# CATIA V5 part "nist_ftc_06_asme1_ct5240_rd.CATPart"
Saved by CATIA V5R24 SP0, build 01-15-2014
Part number: NIST PMI FTC 06 ASME1
Revision: D
Description: NIST PMI test model downloaded from http://go.usa.gov/mGVm
Bounding box of the stored display mesh (mm): x -152.4 to 152.4, y 0 to 97.79, z -247.65 to 0
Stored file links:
  C:\work\NIST\DCC_review\nist_ftc_06_asme1_ct5240_rd.CATPart
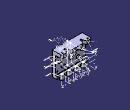
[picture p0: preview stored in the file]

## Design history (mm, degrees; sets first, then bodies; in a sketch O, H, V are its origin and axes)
f4a2d38f3ddc11d3a929006094b99c4b_11 "CATTPSSet"
TTRSSet1
Set1 "Geom_for_MBD_A_notes"
  Plane1: type Equation, A -0.57735, B -0.57735, C 0.57735, Length 229.55, RefPoint vertex [face of Pad1 from Sketch12.L1 | face of Pad1 from Sketch12.L2 | end face of Pad1], RefAxis AxisSystem5
Set2 "MBD_A"
  AxisSystem1 "F1": origin (108.585, 50.8, -209.55), X (-1, 0, 0), Y (0, 1, 0), Z (0, 0, -1)
  AxisSystem2 "F2": origin (36.195, 50.8, -209.55), X (-1, 0, 0), Y (0, 1, 0), Z (0, 0, -1)
  AxisSystem3 "F3": origin (-36.195, 50.8, -209.55), X (-1, 0, 0), Y (0, 1, 0), Z (0, 0, -1)
  AxisSystem4 "F4": origin (-108.585, 50.8, -209.55), X (-1, 0, 0), Y (0, 1, 0), Z (0, 0, -1)
  AxisSystem5 "EAB": origin (0, 0, -209.55), X (-1, 0, 0), Y (0, 0, 1), Z (0, 1, 0)
Set3 "MBD_C"
  AxisSystem6 "DCJ": origin (82.55, 31.75, 0), X (1, 0, 0), Y (0, 0, -1), Z (0, 1, 0)
  AxisSystem7 "DCK": origin (-82.55, 31.75, 0), X (1, 0, 0), Y (0, 0, -1), Z (0, 1, 0)
  AxisSystem8 "DG": origin (76.2, 31.75, -158.75), X (0, 0, -1), Y (-1, 0, 0), Z (0, 1, 0)
  AxisSystem9 "DH": origin (-76.2, 31.75, -158.75), X (0, 0, -1), Y (-1, 0, 0), Z (0, 1, 0)
  Sketch1 on face of Pocket1 from Sketch15.L6, origin (-87.885, 40.9814, 0), H (-0.4226, -0.9063, 0), V (0, 0, 1)
    line L1 (-45.8598, -31.75) -> (-45.8598, 0)
    point P1 (-45.8598, -31.75)
    reference projected point E1 (-45.8598, -31.75) from Sketch10.P5
    vertical: L1 V
    coincidence: P1 E1
  Sketch2 on face of RectPattern2, origin (87.885, 40.9814, 0), H (-0.4226, 0.9063, 0), V (0, 0, 1)
    line L1 (45.8598, -31.75) -> (45.8598, 0)
    point P1 (45.8598, -31.75)
    reference projected point E1 (45.8598, -31.75) from Sketch9.P6
    vertical: L1 V
    coincidence: P1 E1
  Sketch3 on face of RectPattern2, origin (47.7271, -22.2555, 0), H (-0.4226, -0.9063, 0), V (0, 0, 1)
    line L1 (-115.6341, -31.75) -> (-115.6341, 0)
    point P1 (-115.6341, -31.75)
    reference projected point E1 (-115.6341, -31.75) from Sketch9.P5
    vertical: L1 V
    coincidence: P1 E1
  Sketch4 on Plane6, origin (0, 66.04, 0), H (-1, 0, 0), V (0, 0, 1)
    circle A1 centre (76.2, -158.75) radius 12.7
    point P1 (76.2, -158.75)
    reference projected point E1 (76.2, -158.75) from axis of face of RectPattern7
    circle A2 centre (-76.2, -158.75) radius 12.7
    point P2 (-76.2, -158.75)
    reference projected point E2 (-76.2, -158.75) from axis of face of Hole4
    radius A1 = 12.7
    radius A2 = 12.7
    coincidence: E1 P1, E2 P2
  Sketch5 on face of RectPattern2, origin (47.7271, -22.2555, 0), H (-0.4226, -0.9063, 0), V (0, 0, 1)
    projected line E1 (-132.4556, 0) -> (-97.4233, 0) from edge [face of RectPattern2 | face of Pad1 from Sketch12.L1]
    projected line E2 (-132.4556, -31.75) -> (-97.4233, -31.75) from edge [face of Pad1 from Sketch12.L7 | face of RectPattern2]
    line L1 (-97.4233, 0) -> (-115.6341, 0)
    point P5 (-114.9395, 0)
    line L2 (-115.6341, -31.75) -> (-97.4233, -31.75)
    point P6 (-115.6341, -31.75)
    line L3 (-97.4233, 0) -> (-97.4233, -31.75)
    line L4 (-115.6341, 0) -> (-115.6341, -31.75)
    reference projected line E3 (-115.6341, -31.75) -> (-115.6341, 0) from Sketch3
    midpoint: P5 E1
    horizontal: L1 H, L2 H
    coincidence: P6 E2, E3 L4
    vertical: L3 V, L4 V
  Sketch6 on face of RectPattern2, origin (87.885, 40.9814, 0), H (-0.4226, 0.9063, 0), V (0, 0, 1)
    projected line E1 (62.6813, 0) -> (27.6491, 0) from edge [face of Pad1 from Sketch12.L1 | face of RectPattern2]
    projected line E2 (45.8598, 0) -> (27.6491, 0) from edge [face of Pad1 from Sketch12.L1 | face of RectPattern2]
    projected line E3 (27.6491, -31.75) -> (27.6491, 0) from edge [face of RectPattern2 | face of RectPattern2]
    projected line E4 (27.6491, -31.75) -> (62.6813, -31.75) from edge [face of Pad1 from Sketch12.L7 | face of RectPattern2]
    projected line E5 (27.6491, -31.75) -> (45.8598, -31.75) from edge [face of Pad1 from Sketch12.L7 | face of RectPattern2]
    projected line E6 (45.8598, -31.75) -> (45.8598, 0) from Sketch2.L1
  Sketch7 on face of Pocket1 from Sketch15.L6, origin (-87.885, 40.9814, 0), H (-0.4226, -0.9063, 0), V (0, 0, 1)
    projected line E1 (-62.6813, 0) -> (-27.6491, 0) from edge [face of Pocket1 from Sketch15.L6 | face of Pad1 from Sketch12.L1]
    projected line E2 (-45.8598, 0) -> (-27.6491, 0) from edge [face of Pocket1 from Sketch15.L6 | face of Pad1 from Sketch12.L1]
    projected line E3 (-62.6813, -31.75) -> (-27.6491, -31.75) from edge [face of Pad1 from Sketch12.L7 | face of Pocket1 from Sketch15.L6]
    projected line E4 (-45.8598, -31.75) -> (-27.6491, -31.75) from edge [face of Pad1 from Sketch12.L7 | face of Pocket1 from Sketch15.L6]
    projected line E5 (-27.6491, -31.75) -> (-27.6491, 0) from edge [face of Pocket1 from Sketch15.L5 | face of Pocket1 from Sketch15.L6]
    projected line E6 (-45.8598, -31.75) -> (-45.8598, 0) from Sketch1.L1
  Sketch8 on face of Pocket1 from Sketch15.L1, origin (-47.7271, -22.2555, 0), H (-0.4226, 0.9063, 0), V (0, 0, 1)
    projected line E1 (97.4233, -31.75) -> (132.4556, -31.75) from edge [face of Pad1 from Sketch12.L7 | face of Pocket1 from Sketch15.L1]
    projected line E2 (97.4233, -31.75) -> (115.6341, -31.75) from edge [face of Pad1 from Sketch12.L7 | face of Pocket1 from Sketch15.L1]
    projected line E3 (97.4233, -31.75) -> (97.4233, 0) from edge [face of Pocket1 from Sketch15.L1 | face of Pocket1 from Sketch15.L2]
    projected line E4 (132.4556, 0) -> (97.4233, 0) from edge [face of Pad1 from Sketch12.L1 | face of Pocket1 from Sketch15.L1]
    projected line E5 (115.6341, 0) -> (97.4233, 0) from edge [face of Pad1 from Sketch12.L1 | face of Pocket1 from Sketch15.L1]
    projected line E6 (115.6341, -31.75) -> (115.6341, 0) from Sketch11.L1
    construction line L1 through (0, 0) direction (0, 1)
  Sketch9 on face of Pad1 from Sketch12.L7, origin (0, 0, -31.75), H (1, 0, 0), V (0, -1, 0)
    projected line E1 (103.7053, -97.79) -> (88.9, -66.04) from edge [face of Pad1 from Sketch12.L7 | face of RectPattern2]
    projected line E2 (76.2, -66.04) -> (61.3947, -97.79) from edge [face of Pad1 from Sketch12.L7 | face of RectPattern2]
    line L1 (88.9, -66.04) -> (76.2, -66.04)
    line L2 (96.5962, -82.5446) -> (68.5038, -82.5446)
    point P5 (96.5962, -82.5446)
    point P6 (68.5038, -82.5446)
    point P7 (96.5962, -82.5446)
    point P8 (68.5038, -82.5446)
    length L2 = 28.0924
    horizontal: L1 H, L2 H
    coincidence: P5 E1, P6 E2, P7 P5, P8 P6
  Sketch10 on face of Pad1 from Sketch12.L7, origin (0, 0, -31.75), H (1, 0, 0), V (0, -1, 0)
    projected line E1 (-61.3947, -97.79) -> (-76.2, -66.04) from edge [face of Pad1 from Sketch12.L7 | face of Pocket1 from Sketch15.L6]
    projected line E2 (-88.9, -66.04) -> (-103.7053, -97.79) from edge [face of Pad1 from Sketch12.L7 | face of Pocket1 from Sketch15.L1]
    line L1 (-76.2, -66.04) -> (-88.9, -66.04)
    line L2 (-68.5038, -82.5446) -> (-96.5962, -82.5446)
    point P5 (-68.5038, -82.5446)
    point P6 (-96.5962, -82.5446)
    point P7 (-68.5038, -82.5446)
    point P8 (-96.5962, -82.5446)
    length L2 = 28.0924
    horizontal: L1 H, L2 H
    coincidence: P5 E1, P7 P5, P6 E2, P8 P6
  Sketch11 on face of Pocket1 from Sketch15.L1, origin (-47.7271, -22.2555, 0), H (-0.4226, 0.9063, 0), V (0, 0, 1)
    line L1 (115.6341, -31.75) -> (115.6341, 0)
    point P1 (115.6341, -31.75)
    reference projected point E1 (115.6341, -31.75) from Sketch10.P6
    vertical: L1 V
    coincidence: P1 E1
Set4 "MBD_A_B_C"
  AxisSystem10 "DBC": origin (0, 31.75, 0), X (1, 0, 0), Y (0, 0, -1), Z (0, 1, 0)
  AxisSystem11 "ABC": origin (0, 0, 0), X (1, 0, 0), Y (0, 0, -1), Z (0, 1, 0)
Set5
  Plane2: type Offset, RefPlane xy-plane, Offset 247.65, reversed
  Plane3: type Offset, RefPlane zx-plane, Offset 46.99
  Plane4: type Offset, RefPlane yz-plane, Offset 76.2
  Plane5: type Offset, RefPlane yz-plane, Offset 114.3
  Point1: type OnCurve, Support edge [face of Pad1 from Sketch12.L7 | face of Pocket1 from Sketch15.L1], Length 18.2093
  Point2: type OnCurve, Support edge [face of Pad1 from Sketch12.L7 | face of Pocket1 from Sketch15.L6], Length 18.2093
  Point3: type OnCurve, Support edge [face of Pad1 from Sketch12.L7 | face of RectPattern2], Length 18.2093
  Point4: type OnCurve, Support edge [face of Pad1 from Sketch12.L7 | face of RectPattern2], Length 18.2093
  Plane6: type Offset, RefPlane zx-plane, Offset 66.04
  Plane7: type Angle, RefPlane xy-plane, Direction edge [face of Pad1 from Sketch12.L2 | face of Pad1 from Sketch12.L1], Angle 45
  Point5: type OnCurve, Support edge [face of Pad1 from Sketch12.L2 | face of Pad1 from Sketch12.L1], Length 152.4
  Point6: type OnPlane, Support face of Pad1 from Sketch12.L6, H 0, V 0, Direction (-1, 0, 0)
  Point7: type Center, Curve edge [face of RectPattern1 | face of Hole3]
  Point8: type Center, Curve edge [face of RectPattern1 | face of RectPattern5]
  Point9: type Center, Curve edge [face of RectPattern1 | face of RectPattern5]
  Point10: type Center, Curve edge [face of RectPattern1 | face of RectPattern5]
  Point11: type OnCurve, Support edge [face of Fillet1 | face of Pad1 from Sketch12.L6], RefPoint {extremum Reference edge [face of Fillet1 | face of Pad1 from Sketch12.L6], Direction (1, 2, 3)}, Length 65.977
  Point12: type OnCurve, Support edge [face of Fillet1 | face of Pad1 from Sketch12.L6], RefPoint {extremum Reference edge [face of Fillet1 | face of Pad1 from Sketch12.L6], Direction (1, 2, 3)}, Length 65.9892
  Point13: type OnPlane, Support face of Pad1 from Sketch12.L1, H 82.55, V 31.75, Direction (1, 0, 0)
  Point14: type OnPlane, Support face of Pad1 from Sketch12.L1, H -82.55, V 31.75, Direction (1, 0, 0)
  Plane8: type Offset, RefPlane face of Pad1 from Sketch12.L2, Offset 82.55
  Plane9: type Offset, RefPlane face of Pad1 from Sketch12.L2, Offset 66.04
  Point15: type OnSurface, Support face of Fillet1, Length 0, Direction (-0.9567, 0.021, -0.2904)
  Plane10: type Offset, RefPlane face of Pad1 from Sketch12.L1, Offset 107.95
  Point16: type OnPlane, Support face of Pad1 from Sketch12.L6, H -76.2, V -158.75, Direction (-1, 0, 0)
  Point17: type OnPlane, Support face of Pad1 from Sketch12.L6, H 76.2, V -158.75, Direction (-1, 0, 0)
  Point18: type OnPlane, Support face of Pad1 from Sketch12.L2, H 0, V -209.55, Direction (1, 0, 0)
  Plane11: type Offset, RefPlane face of Pad1 from Sketch12.L8, Offset 0, reversed
Body1 (main body)
  Sketch12 on yz-plane, origin (0, 0, 0), H (0, 1, 0), V (0, 0, 1)
    point P1 (97.79, 0)
    line L1 (97.79, 0) -> (0, 0)
    line L2 (0, 0) -> (0, -234.95)
    line L3 (0, -234.95) -> (50.8, -234.95)
    line L4 (50.8, -234.95) -> (50.8, -209.55)
    line L5 (50.8, -209.55) -> (31.75, -209.55)
    line L6 (31.75, -209.55) -> (31.75, -31.75)
    line L7 (31.75, -31.75) -> (97.79, -31.75)
    line L8 (97.79, -31.75) -> (97.79, 0)
    length L2 = 234.95
    distance L1 L5 = 209.55
    distance L1 L7 = 31.75
    distance L2 L6 = 31.75
    distance L4 L2 = 50.8
    distance L2 L8 = 97.79
    coincidence: P1 H
    horizontal: L1 H, L3 H, L5 H, L7 H
    vertical: L2 V, L4 V, L6 V, L8 V
  Pad1: profile Sketch12, direction (1, 0, 0), length 152.4, mirrored extent
  Sketch13 on yz-plane, origin (0, 0, 0), H (0, 1, 0), V (0, 0, 1)
    line L1 (97.79, -31.75) -> (46.99, -133.35)
    point P1 (97.79, -31.75)
    point P2 (46.99, -133.35)
    line L2 (46.99, -133.35) -> (31.75, -133.35)
    point P3 (31.75, -133.35)
    reference projected point E1 (97.79, -31.75) from vertex [face of Pad1 from Sketch12.L8 | end face of Pad1 | face of Pad1 from Sketch12.L7]
    reference projected point E2 (97.79, -31.75) from vertex [face of Pad1 from Sketch12.L8 | end face of Pad1 | face of Pad1 from Sketch12.L7]
    reference projected line E3 (31.75, -31.75) -> (97.79, -31.75) from edge [face of Pad1 from Sketch12.L7 | end face of Pad1]
    reference projected line E4 (97.79, -31.75) -> (97.79, 0) from edge [face of Pad1 from Sketch12.L8 | end face of Pad1]
    reference intersected line E5 (31.75, -31.75) -> (31.75, -209.55) from face of Pad1 from Sketch12.L6
    distance E3 L2 = 101.6
    distance P2 E4 = 50.8
    coincidence: E1 L1, E2 P1, E5 P3
  Stiffener1: ExtendedProfile Sketch13, ThicknessTop 0, ThicknessValue 25.4
  Sketch14 on Plane2, origin (0, 0, -247.65), H (1, 0, 0), V (0, 1, 0)
    circle A1 centre (108.585, 50.8) radius 22.225
    point P1 (108.585, 50.8)
    reference projected line E1 (-152.4, 0) -> (152.4, 0) from edge [face of Pad1 from Sketch12.L3 | face of Pad1 from Sketch12.L2]
    reference intersected line E2 through (152.4, 0) direction (0, 1) from end face of Pad1
    distance P1 E1 = 50.8
    radius A1 = 22.225
    distance E2 P1 = 43.815
  Pad2: profile Sketch14, direction (0, 0, 1), length 38.1
  RectPattern1: of Pad2, direction 1 instances 4, spacing 72.39, along edge [face of Pad1 from Sketch12.L4 | face of Pad1 from Sketch12.L3] reversed
  Sketch15 on face of Pad1 from Sketch12.L7, origin (0, 0, -31.75), H (1, 0, 0), V (0, -1, 0)
    line L1 (-103.7053, -97.79) -> (-88.9, -66.04)
    point P1 (-88.9, -66.04)
    line L2 (-88.9, -66.04) -> (-88.9, -52.07)
    line L3 (-88.9, -52.07) -> (-76.2, -52.07)
    reference intersected line E1 (-152.4, 0) -> (152.4, 0) from face of Pad1 from Sketch12.L2
    axis line L4 (-82.55, -52.07) -> (-82.55, -133.5251)
    reference intersected line E2 (-152.4, 0) -> (152.4, 0) from face of Pad1 from Sketch12.L2
    point P7 (-76.2, -66.04)
    line L5 (-76.2, -66.04) -> (-76.2, -52.07)
    line L6 (-61.3947, -97.79) -> (-76.2, -66.04)
    reference intersected line E3 through (0, 0) direction (0, 1) from yz-plane
    projected line E4 (-152.4, -97.79) -> (-12.7, -97.79) from edge [face of Pad1 from Sketch12.L8 | face of Pad1 from Sketch12.L7]
    projected line E5 (-103.7053, -97.79) -> (-61.3947, -97.79) from edge [face of Pad1 from Sketch12.L8 | face of Pad1 from Sketch12.L7]
    distance E1 L3 = 52.07
    length L3 = 12.7
    distance L2 L4 = 6.35
    distance E2 P1 = 66.04
    distance E2 P7 = 66.04
    distance L5 L4 = 6.35
    angle L1 L6 = 50
    distance E3 L4 = 82.55
    angle L1 L4 = 25
  Pocket1: profile Sketch15, direction (0, 0, 1), through (limit type 6)
  RectPattern2: of Pocket1, direction 1 instances 2, spacing 165.1, along edge [face of Pad1 from Sketch12.L8 | face of Pad1 from Sketch12.L7]
  Sketch16 on Plane3, origin (0, 46.99, 0), H (0, 0, 1), V (1, 0, 0)
    circle A1 centre (-158.75, 76.2) radius 15.875
    point P1 (-158.75, 76.2)
    reference projected line E1 (0, -152.4) -> (0, 152.4) from edge [face of Pad1 from Sketch12.L1 | face of Pad1 from Sketch12.L8]
    reference intersected line E2 through (0, 0) direction (-1, 0) from yz-plane
    radius A1 = 15.875
    distance E1 P1 = 158.75
    distance E2 P1 = 76.2
  Pad3: profile Sketch16, direction (0, -1, 0), up to face of Pad1 from Sketch12.L6
  Sketch17 on Plane4, origin (76.2, 0, 0), H (0, 1, 0), V (0, 0, 1)
    axis line L1 (47.3647, -158.75) -> (174.207, -158.75)
    reference intersected line E1 (0, 0) -> (97.79, 0) from face of Pad1 from Sketch12.L1
    point P3 (46.99, -174.625)
    line L2 (46.99, -174.625) -> (85.09, -168.275)
    line L3 (85.09, -168.275) -> (85.09, -158.75)
    line L4 (85.09, -158.75) -> (46.99, -158.75)
    reference intersected line E2 (0, -234.95) -> (0, 0) from face of Pad1 from Sketch12.L2
    projected line E3 (46.99, -142.875) -> (46.99, -174.625) from edge [face of Pad3 from Sketch16.A1 | start face of Pad3]
    projected line E4 (46.99, -158.75) -> (46.99, -174.625) from edge [face of Pad3 from Sketch16.A1 | start face of Pad3]
    point P7 (46.99, -174.625)
    distance E1 L1 = 158.75
    distance L3 E2 = 85.09
    length L3 = 9.525
    coincidence: P3 P7, L1 L4
  Shaft1: profile Sketch17, axis Sketch17.L1, angle 360
  Sketch18 on Plane5, origin (114.3, 0, 0), H (0, 1, 0), V (0, 0, 1)
    axis line L1 (-156.5, -107.95) -> (163.5, -107.95)
    arc A1 centre (63.5, -107.95) radius 15.875 from (79.375, -107.95) to (47.625, -107.95) ccw
    point P3 (63.5, -107.95)
    reference projected line E1 (97.79, 0) -> (0, 0) from edge [face of Pad1 from Sketch12.L1 | end face of Pad1]
    reference projected line E2 (0, 0) -> (0, -234.95) from edge [face of Pad1 from Sketch12.L2 | end face of Pad1]
    distance P3 E1 = 107.95
    distance E2 P3 = 63.5
    radius A1 = 15.875
    coincidence: P3 L1
  Shaft2: profile Sketch18, axis Sketch18.L1, angle 360
  Sketch19 on face of Pad1 from Sketch12.L6, origin (0, 31.75, 0), H (-1, 0, 0), V (0, 0, 1)
    circle A1 centre (-114.3, -107.95) radius 11.43
    point P1 (-114.3, -107.95)
    reference intersected line E1 (-152.4, 0) -> (152.4, 0) from face of Pad1 from Sketch12.L1
    reference intersected line E2 through (0, 0) direction (0, -1) from yz-plane
    distance P1 E1 = 107.95
    distance P1 E2 = 114.3
    radius A1 = 11.43
  Pad4: profile Sketch19, direction (0, 1, 0), up to face of Shaft2 from Sketch18.A1
  Sketch20 on face of Pad1 from Sketch12.L7, origin (129.0197, 80.9562, -31.75), H (1, 0, 0), V (0, -1, 0)
    point P1 (-2.0197, 2.2162)
    reference intersected line E1 through (-129.0197, 0) direction (0, 1) from yz-plane
    reference intersected line E2 (23.3803, -16.8338) -> (-281.4197, -16.8338) from face of Pad1 from Sketch12.L8
    distance E1 P1 = 127
    distance P1 E2 = 19.05
  Hole1: placed by Sketch20, at (127, 78.74, -31.75) direction (0, 0, 1), diameter 14.2875, through (limit type 6), counterbore diameter 20.6375, counterbore depth 14.2875
  RectPattern3: of Hole1, direction 1 instances 2, spacing 254, along edge [face of Pad1 from Sketch12.L8 | face of Pad1 from Sketch12.L7] reversed
  Sketch21 on face of Pad1 from Sketch12.L6, origin (123.0782, 31.75, -62.8696), H (1, 0, 0), V (0, 0, -1)
    point P1 (10.2718, -5.7196)
    reference projected line E1 (-275.4782, -62.8696) -> (29.3218, -62.8696) from edge [face of Pad1 from Sketch12.L1 | face of Pad1 from Sketch12.L8]
    reference intersected line E2 through (-123.0782, 0) direction (0, 1) from yz-plane
    distance E1 P1 = 57.15
    distance E2 P1 = 133.35
  Hole2: placed by Sketch21, at (133.35, 31.75, -57.15) direction (0, -1, 0), diameter 10.541, through (limit type 6), counterbore diameter 15.875, counterbore depth 12.7
  RectPattern4: of Hole2, direction 1 instances 2, spacing 266.7, along edge [face of Pad1 from Sketch12.L8 | face of Pad1 from Sketch12.L7] reversed, direction 2 instances 2, spacing 127, along edge [face of Pad1 from Sketch12.L6 | end face of Pad1] reversed
  Sketch22 on start face of Pad2, origin (108.585, 50.8, -247.65), H (1, 0, 0), V (0, -1, 0)
    point P1 (0, 0)
  Hole3: placed by Sketch22, at (108.585, 50.8, -247.65) direction (0, 0, 1), diameter 7.1374, through (limit type 6), counterbore diameter 10.16, counterbore depth 7.9375
  RectPattern5: of Hole3, direction 1 instances 4, spacing 72.39, along edge [face of Pad1 from Sketch12.L4 | face of Pad1 from Sketch12.L3] reversed, direction 2 instances 2, spacing 127
  RectPattern6: of Pad3, Sketch16, Shaft1, Sketch17, direction 1 instances 2, spacing 152.4, along edge [face of Pad1 from Sketch12.L8 | face of Pad1 from Sketch12.L7] reversed, direction 2 instances 2, spacing 127
  Sketch23 on face of Shaft1 from Sketch17.L3, origin (76.2, 85.09, -158.75), H (1, 0, 0), V (0, 0, -1)
    point P1 (0, 0)
    coincidence: P1 O
  Hole4: placed by Sketch23, at (76.2, 85.09, -158.75) direction (0, -1, 0), diameter 6.35, depth 12.7, V-bottom angle 118
  RectPattern7: of Hole4, direction 1 instances 2, spacing 152.4, along edge [face of Pad1 from Sketch12.L4 | face of Pad1 from Sketch12.L3] reversed, direction 2 instances 2, spacing 127
  Fillet1: radius 3.175, on edge [face of Pad1 from Sketch12.L7 | face of Pad1 from Sketch12.L6] (x2); edge [face of Stiffener1 | face of Pad1 from Sketch12.L7]; edge [face of Pad1 from Sketch12.L6 | face of Stiffener1]; edge [face of Stiffener1 from Sketch13.L2 | face of Pad1 from Sketch12.L6]; edge [face of Stiffener1 | face of Pad1 from Sketch12.L6]; edge [face of Pad1 from Sketch12.L7 | face of Stiffener1]; edge [face of Pad1 from Sketch12.L6 | face of RectPattern6]; edge [face of Pad1 from Sketch12.L6 | face of Pad3 from Sketch16.A1]; edge [face of Pad1 from Sketch12.L6 | face of RectPattern1]; edge [face of Pad1 from Sketch12.L4 | face of Pad2 from Sketch14.A1]; edge [face of Pad2 from Sketch14.A1 | face of Pad1 from Sketch12.L4]; edge [face of RectPattern1 | face of Pad1 from Sketch12.L4] (x3); edge [face of Pad1 from Sketch12.L4 | face of RectPattern1] (x3)
  Sketch24 on face of Pad1 from Sketch12.L8, origin (0, 97.79, 0), H (-1, 0, 0), V (0, 0, 1)
    arc A1 centre (0, -15.875) radius 12.7 from (0, -28.575) to (0, -3.175) ccw
    point P1 (0, -15.875)
    reference intersected line E1 through (0, 0) direction (0, -1) from yz-plane
    reference intersected line E2 (152.4, -31.75) -> (-152.4, -31.75) from face of Pad1 from Sketch12.L7
    line L1 (0, -3.175) -> (0, -28.575)
    radius A1 = 12.7
    distance E2 P1 = 15.875
    coincidence: E1 P1, P1 L1
    vertical: L1 V
  Fillet2: radius 12.7, on edge [start face of Pad1 | face of Pad1 from Sketch12.L8]; edge [face of Pad1 from Sketch12.L8 | end face of Pad1]
  Groove1: profile Sketch24, axis Sketch24.L1, angle 360
  Sketch25 on Plane10, origin (0, 97.79, -107.95), H (0, 1, 0), V (1, 0, 0)
    line L1 (-66.04, -114.3) -> (-18.415, -114.3)
    point P1 (-162.8215, -114.3)
    point P2 (-2.54, -114.3)
    line L2 (-66.04, -114.3) -> (-66.04, -125.73)
    line L3 (-66.04, -125.73) -> (-45.3068, -125.73)
    arc A1 centre (-34.29, -114.3) radius 15.875 from (-45.3068, -125.73) to (-18.415, -114.3) ccw
    point P5 (-34.29, -114.3)
    reference intersected line E1 (-66.04, 152.4) -> (-66.04, -152.4) from face of Pad1 from Sketch12.L6
    reference intersected line E2 through (0, 0) direction (-1, 0) from yz-plane
    reference intersected line E3 (-97.79, -152.4) -> (-97.79, 152.4) from face of Pad1 from Sketch12.L2
    radius A1 = 15.875
    distance E2 L1 = 114.3
    distance L1 L3 = 11.43
    distance P5 E3 = 63.5
    horizontal: L1 H, L3 H
    vertical: L2 V
    coincidence: E1 L2, P1 L1, L1 P5
  Shaft3: profile Sketch25, axis Sketch25.L1, angle 360
  Fillet3: radius 3.175, on edge [face of Pad4 from Sketch19.A1 | face of Shaft2 from Sketch18.A1]; edge [face of Pad1 from Sketch12.L6 | face of Pad4 from Sketch19.A1]
  Fillet4: radius 3.175, on edge [face of Shaft3 from Sketch25.A1 | face of Shaft3 from Sketch25.L3]; edge [face of Shaft3 from Sketch25.L3 | face of Pad1 from Sketch12.L6]
  Sketch26 "Main View" on face of Pad1 from Sketch12.L3, origin (0, 0, -234.95), H (-1, 0, 0), V (0, 1, 0)
    point P1 (-27.9401, 6.35)
    point P2 (-14.4332, 7.6694)
    point P3 (-8.1701, 9.8671)
    point P4 (-3.0267, 10.5457)
    point P5 (-1.9341, 9.4532)
    point P6 (-24.8376, 6.35)
    point P7 (-27.9401, 6.35)
    point P8 (-24.8376, 17.5935)
    point P9 (-24.8376, 6.35)
    point P10 (-23.9004, 17.959)
    point P11 (-24.8376, 17.5935)
    point P12 (-14.4332, 7.6694)
    point P13 (-23.9004, 17.959)
    point P14 (-8.1701, 21.35)
    point P15 (-8.1701, 9.8671)
    point P16 (-11.3024, 21.35)
    point P17 (-8.1701, 21.35)
    point P18 (-11.3024, 9.9419)
    point P19 (-11.3024, 21.35)
    point P20 (-12.02, 9.6257)
    point P21 (-11.3024, 9.9419)
    point P22 (-22.2849, 20.7261)
    point P23 (-12.02, 9.6257)
    point P24 (-22.2849, 20.7261)
    point P25 (-27.9401, 18.5121)
    point P26 (-27.9401, 6.35)
    point P27 (-27.9401, 18.5121)
    point P28 (-3.0267, 21.35)
    point P29 (-6.159, 21.35)
    point P30 (-3.0267, 10.5457)
    point P31 (-3.0267, 21.35)
    point P32 (12.7773, 9.4532)
    point P33 (-1.9341, 9.4532)
    point P34 (12.7773, 9.4532)
    point P35 (12.7198, 12.2696)
    point P36 (3.668, 12.2696)
    point P37 (12.7198, 12.2696)
    point P38 (3.3241, 21.35)
    point P39 (3.668, 12.2696)
    point P40 (28.9273, 21.35)
    point P41 (3.3241, 21.35)
    point P42 (28.9273, 18.189)
    point P43 (28.9273, 21.35)
    point P44 (22.5181, 18.189)
    point P45 (28.9273, 18.189)
    point P46 (22.5181, 6.35)
    point P47 (22.5181, 18.189)
    point P48 (19.4156, 6.35)
    point P49 (22.5181, 6.35)
    point P50 (19.4156, 18.189)
    point P51 (19.4156, 6.35)
    point P52 (3.7255, 18.189)
    point P53 (19.4156, 18.189)
    point P54 (3.7255, 18.189)
    point P55 (3.6105, 15.3729)
    point P56 (13.2373, 15.3729)
    point P57 (3.6105, 15.3729)
    point P58 (13.2373, 6.35)
    point P59 (13.2373, 15.3729)
    point P60 (-1.9632, 6.35)
    point P61 (13.2373, 6.35)
    point P62 (-6.159, 10.5457)
    point P63 (-1.9632, 6.35)
    point P64 (-6.159, 21.35)
    point P65 (-6.159, 10.5457)
    line L1 (-6.159, 21.35) -> (-6.159, 10.5457)
    arc A1 centre (-1.9632, 10.5457) radius 4.1957 from (-6.159, 10.5457) to (-1.9632, 6.35) ccw
    line L2 (-1.9632, 6.35) -> (13.2373, 6.35)
    arc A2 centre (12.5188, 10.8615) radius 4.5683 from (13.2373, 6.35) to (13.2373, 15.3729) ccw
    line L3 (13.2373, 15.3729) -> (3.6105, 15.3729)
    arc A3 centre (3.6105, 16.7833) radius 1.4104 from (3.7255, 18.189) to (3.6105, 15.3729) ccw
    line L4 (3.7255, 18.189) -> (19.4156, 18.189)
    line L5 (19.4156, 18.189) -> (19.4156, 6.35)
    line L6 (19.4156, 6.35) -> (22.5181, 6.35)
    line L7 (22.5181, 6.35) -> (22.5181, 18.189)
    line L8 (22.5181, 18.189) -> (28.9273, 18.189)
    line L9 (28.9273, 18.189) -> (28.9273, 21.35)
    line L10 (28.9273, 21.35) -> (3.3241, 21.35)
    arc A4 centre (3.3241, 16.8033) radius 4.5467 from (3.3241, 21.35) to (3.668, 12.2696) ccw
    line L11 (3.668, 12.2696) -> (12.7198, 12.2696)
    arc A5 centre (12.5971, 10.8583) radius 1.4166 from (12.7773, 9.4532) to (12.7198, 12.2696) ccw
    line L12 (12.7773, 9.4532) -> (-1.9341, 9.4532)
    line L13 (-3.0267, 10.5457) -> (-3.0267, 21.35)
    line L14 (-3.0267, 21.35) -> (-6.159, 21.35)
    line L15 (-27.9401, 6.35) -> (-27.9401, 18.5121)
    arc A6 centre (-24.6791, 18.5121) radius 3.261 from (-22.2849, 20.7261) to (-27.9401, 18.5121) ccw
    line L16 (-22.2849, 20.7261) -> (-12.02, 9.6257)
    arc A7 centre (-11.7156, 9.9072) radius 0.4146 from (-12.02, 9.6257) to (-11.3024, 9.9419) ccw
    line L17 (-11.3024, 9.9419) -> (-11.3024, 21.35)
    line L18 (-11.3024, 21.35) -> (-8.1701, 21.35)
    line L19 (-8.1701, 21.35) -> (-8.1701, 9.8671)
    line L20 (-14.4332, 7.6694) -> (-23.9004, 17.959)
    arc A8 centre (-24.2977, 17.5935) radius 0.5399 from (-23.9004, 17.959) to (-24.8376, 17.5935) ccw
    line L21 (-24.8376, 17.5935) -> (-24.8376, 6.35)
    line L22 (-24.8376, 6.35) -> (-27.9401, 6.35)
    arc A9 centre (-1.9341, 10.5457) radius 1.0926 from (-3.0267, 10.5457) to (-1.9341, 9.4532) ccw
    arc A10 centre (-11.6873, 9.8671) radius 3.5171 from (-14.4332, 7.6694) to (-8.1701, 9.8671) ccw
    distance P1 H = 6.35
    distance P1 V = 27.94
    fix: P2, P3, P4, P5, P6, P8, P9, P10, P11, P12, P13, P14, P15, P16, P17, P18, P19, P20, P21, P22, P23, P24, P25, P27, P28, P29, P30, P31, P32, P33, P34, P35, P36, P37, P38, P39, P40, P41, P42, P43, P44, P45, P46, P47, P48, P49, P50, P51, P52, P53, P54, P55, P56, P57, P58, P59, P60, P61, P62, P63, P64, P65, P1, P7, L1, A1, L2, A2, L3, A3, L4, L5, L6, L7, L8, L9, L10, A4, L11, A5, L12, L13, L14, L15, A6, L16, A7, L17, L18, L19, L20, A8, L21, L22, A9, A10, P26
  Pocket2: profile Sketch26, direction (0, 0, 1), length 2.54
